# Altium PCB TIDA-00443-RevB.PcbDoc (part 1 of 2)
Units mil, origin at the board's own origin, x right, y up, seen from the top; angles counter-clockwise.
Board outline 5881 x 3685.61 mil, 2 copper layers (Top Layer, Bottom Layer), stack 62 mil thick; 123 components, 50 nets, 265 pads, 37 vias.
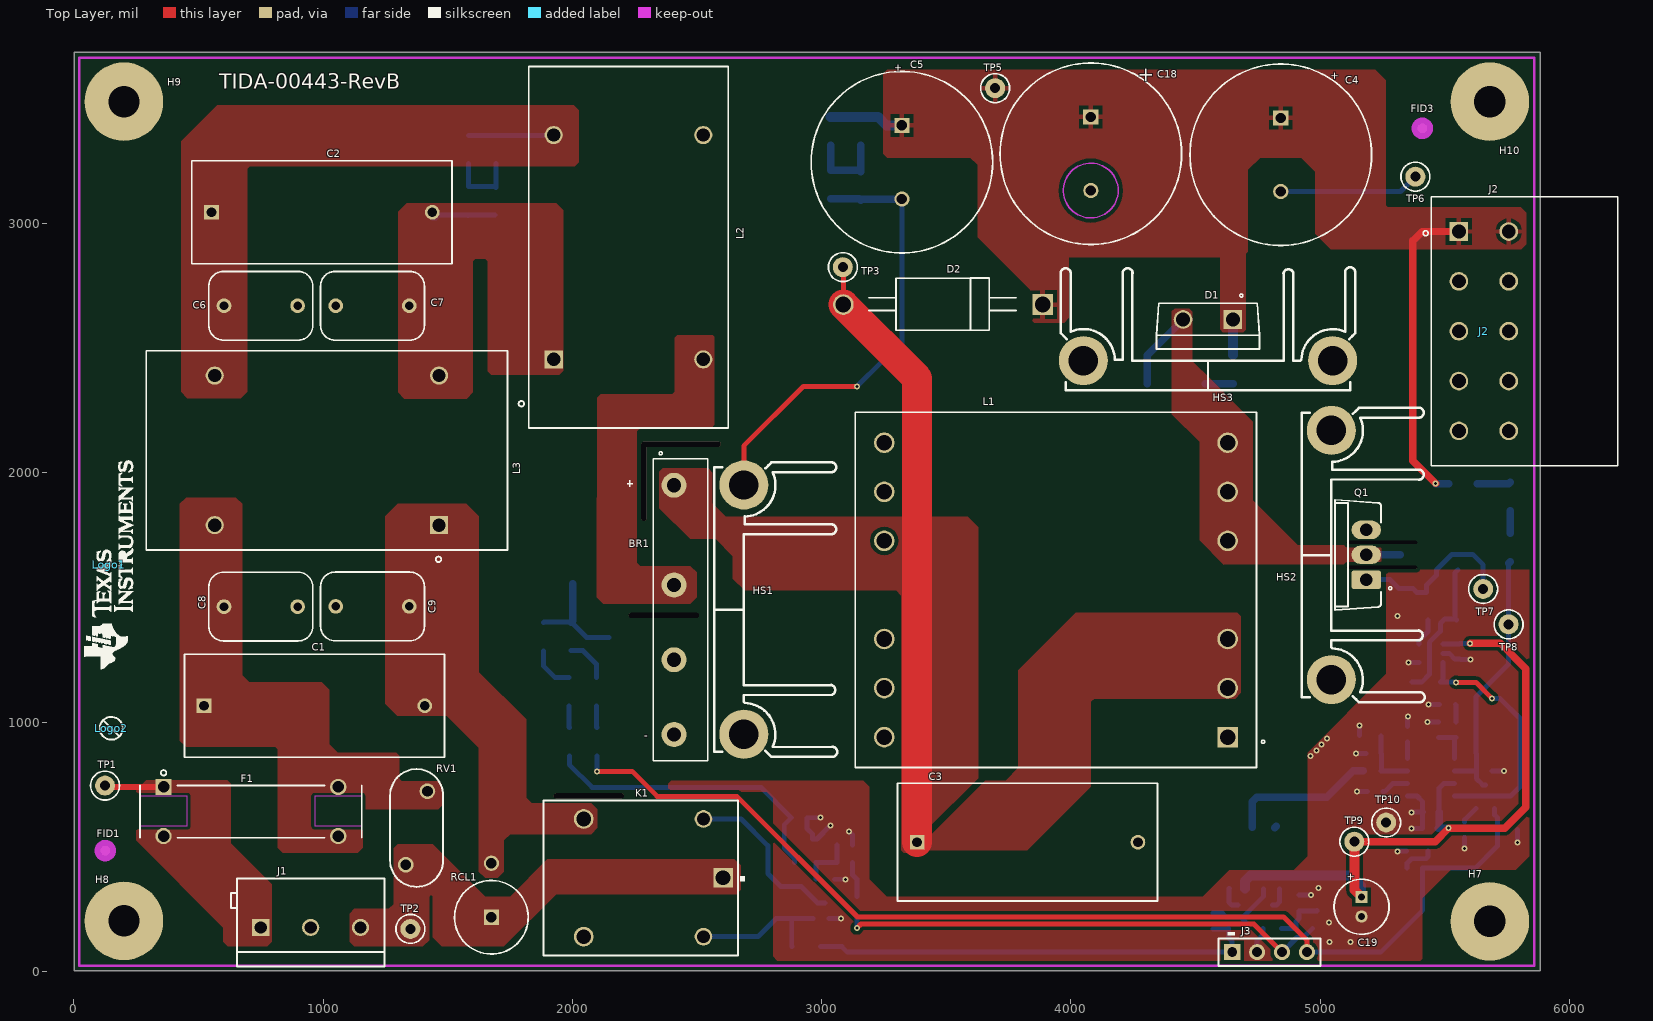
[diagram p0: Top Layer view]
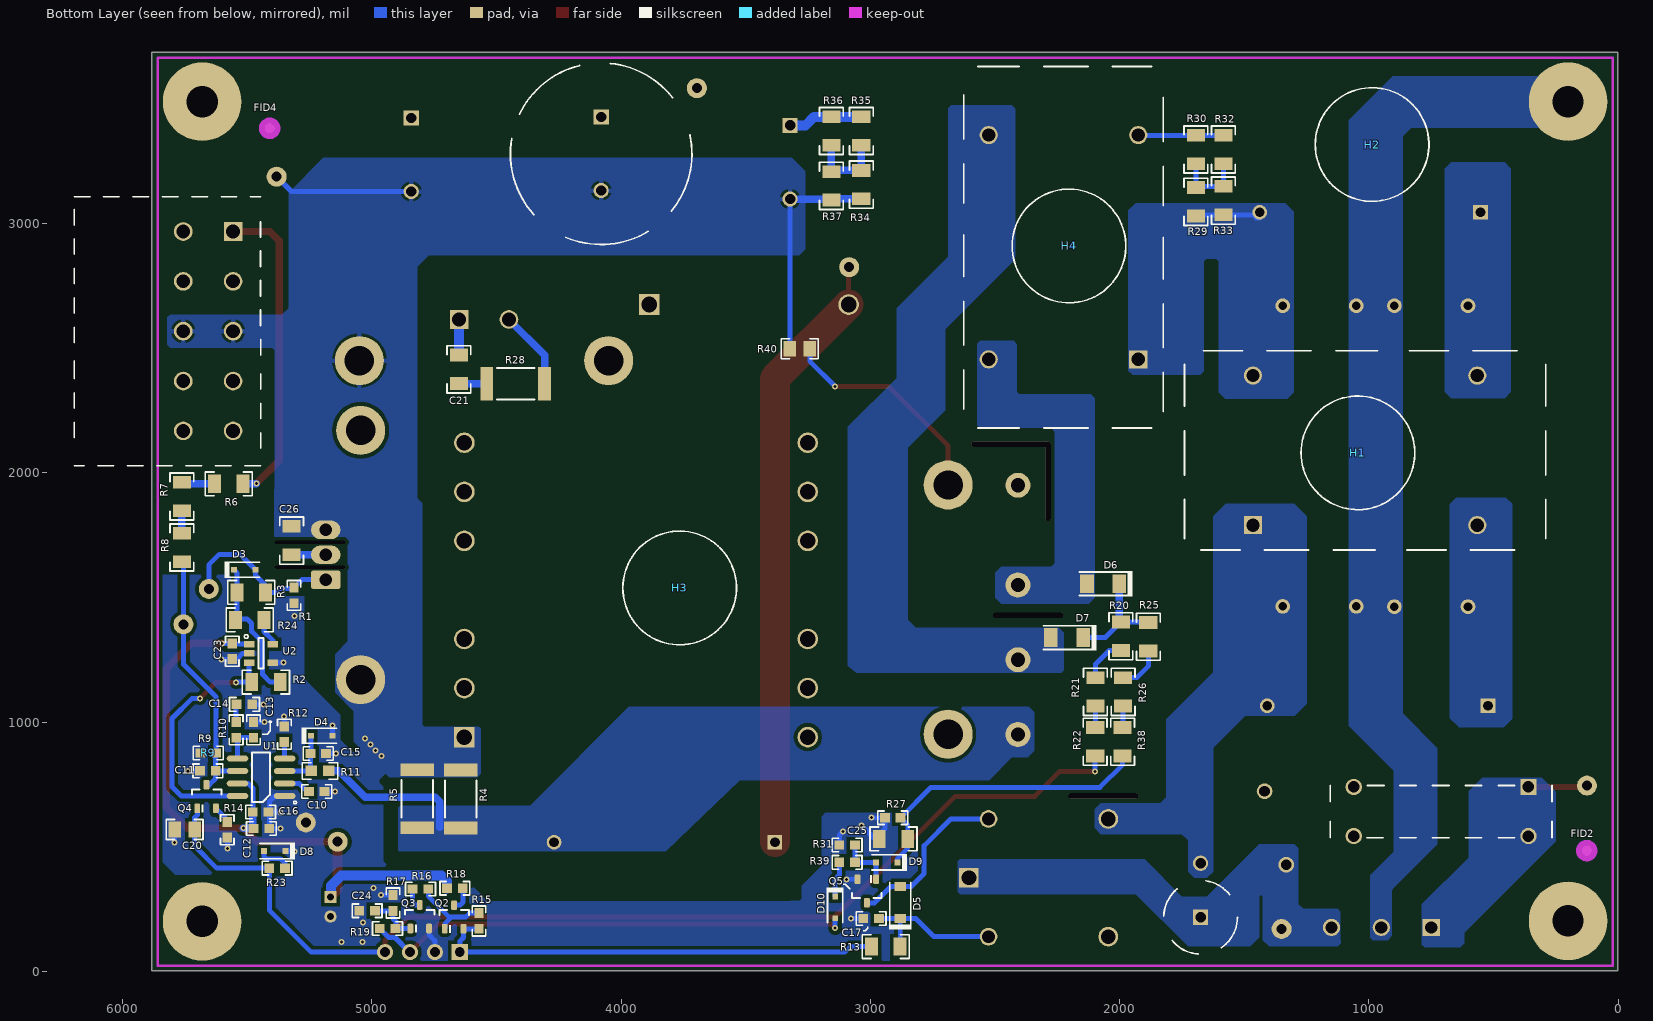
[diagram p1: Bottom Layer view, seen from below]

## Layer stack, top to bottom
Top Layer: signal copper 1.4
Dielectric: core 59.2, FR-4, Dk 4.8
Bottom Layer: signal copper 1.4

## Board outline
1,2 1,3687.61 5882,3687.61 5882,2

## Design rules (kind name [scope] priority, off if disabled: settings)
AcuteAngle [All] p1: minimum=4.50000000000000E+0001 checktracksonly=FALSE
AssemblyTestPointUsage [All] p1: valid=2
Clearance Clearance_net1 [InNet('NetC26_1') vs InPolygon] p1: gap=25
Clearance "Clearance_on net" [InNet('GNDE') vs InNetClass('All Nets')] p2: gap=120
Clearance Clearance_Pad_Via [IsPad vs IsVia] p3: gap=8
Clearance Clearance_Poly_Poly [InPolygon vs InPolygon] p4: gap=20
Clearance Clearance_Poly [InPolygon] p5: gap=15
Clearance [All] p6: gap=8
ComponentClearance ComponentClearance_MountingHoles_FiducialMarks [InComponentClass('Mounting Holes') vs InComponentClass('FiducialMark')] p1: gap=50 collisioncheckmode=3 verticalgap=10 showdistances=FALSE
ComponentClearance ComponentClearance_Shunt [InComponentClass('Header') vs InComponentClass('Shunt')] p2: gap=0 collisioncheckmode=3 verticalgap=0 showdistances=FALSE
ComponentClearance ComponentClearance_Logo [InComponentClass('Logo')] p3: gap=50 collisioncheckmode=3 verticalgap=10 showdistances=FALSE
ComponentClearance ComponentClearance_ScrewToNut [(HasFootprint('NY PMS 440 0025 PH')) vs (HasFootprint('Keystone_1902C'))] p4: gap=5 collisioncheckmode=3 verticalgap=10 showdistances=FALSE
ComponentClearance ComponentClearance_MountingHoles [InComponentClass('Mounting Holes')] p5: gap=200 collisioncheckmode=3 verticalgap=150 showdistances=FALSE
ComponentClearance ComponentClearance_SmallPassives [HasFootprint('0201*') or HasFootprint('0402*') or HasFootprint('0508') or HasFootprint('0603*') or HasFootprint('0612') or HasFootprint('0805*') or HasFootprint('0815*') or HasFootprint('0830*') or HasFootprint('1206*') or HasFootprint('1210*') or HasFootprint('1808*') or HasFootprint('1812*') or HasFootprint('1825*') or HasFootprint('2010*') or HasFootprint('2220*') or HasFootprint('2225*') or HasFootprint('2512*') or HasFootprint('2728*') or HasFootprint('3518*') vs HasFootprint('0201*') or HasFootprint('0402*') or HasFootprint('0508') or HasFootprint('0603*') or HasFootprint('0612') or HasFootprint('0805*') or HasFootprint('0815*') or HasFootprint('0830*') or HasFootprint('1206*') or HasFootprint('1210*') or HasFootprint('1808*') or HasFootprint('1812*') or HasFootprint('1825*') or HasFootprint('2010*') or HasFootprint('2220*') or HasFootprint('2225*') or HasFootprint('2512*') or HasFootprint('2728*') or HasFootprint('3518*')] p6: gap=20 collisioncheckmode=3 verticalgap=10 showdistances=FALSE
ComponentClearance ComponentClearance_THtoSMT [IsThruComponent vs IsSMTComponent] p7: gap=20 collisioncheckmode=3 verticalgap=20 showdistances=FALSE
ComponentClearance ComponentClearance_THtoTH [IsThruComponent vs IsThruComponent] p8: gap=10 collisioncheckmode=3 verticalgap=10 showdistances=FALSE
ComponentClearance [All] p9: gap=20 collisioncheckmode=3 verticalgap=10 showdistances=FALSE
DiffPairsRouting [All] p1: maxlimit=100 minlimit=10 mostfreqgap=10 maxuncoupledlength=1000
FabricationTestPointUsage TestPointUsage [All] p1: valid=2 allowmultiple=FALSE
FabricationTestpoint Testpoint [All] p1: side=3 testpointundercomponent=TRUE minsize=40 maxsize=100 preferedsize=60 minholesize=0 maxholesize=40 preferedholesize=32 testpointgrid=1 allowsidetop=TRUE allowsidebottom=TRUE usegrid=TRUE gridtolerance=0.01
FanoutControl Fanout_LCC [IsLCC] p1: bgadir=Out bgaviamode=Centered fanoutstyle=Auto fanoutdirection=Alternating viagrid=1 // Fanout_LCC (Default Rule)
FanoutControl Fanout_BGA [IsBGA] p2: bgadir=Out bgaviamode=Centered fanoutstyle=Auto fanoutdirection=Alternating viagrid=1 // Fanout_BGA (Default Rule)
FanoutControl Fanout_Default [All] p4: bgadir=Out bgaviamode=Centered fanoutstyle=Auto fanoutdirection=Alternating viagrid=1 // Fanout_Default (Default Rule)
FanoutControl Fanout_Small [(CompPinCount < 5)] p5: bgadir=Out bgaviamode=Centered fanoutstyle=Auto fanoutdirection=OutThenIn viagrid=1 // Fanout_Small (Default Rule)
Height [All] p1: minheight=0 maxheight=2100 prefheight=500
HoleSize [All] p1: absolutevalues=TRUE maxlimit=251 minlimit=8 maxpercent=80.000 minpercent=20.000
MinimumAnnularRing MinimumAnnularRing_ThermalPadVias [IsVia and InAnyComponent] p1: minimumring=5.91
MinimumAnnularRing [All] p2: minimumring=9
MinimumSolderMaskSliver MinimumSolderMaskSliver_Logo [InComponentClass('Logo') vs InComponentClass('Logo')] p1 off: minsoldermaskwidth=0.7
MinimumSolderMaskSliver [All] p2 off: minsoldermaskwidth=3.94
PlaneConnect [All] p1: planeconnectstyle=Direct reliefexpansion=10 reliefentries=4 reliefconductorwidth=10 reliefairgap=10
PolygonConnect PolygonConnect_1 [(InNetClass('New Class'))] p1: connectstyle=Relief reliefconductorwidth=20 reliefentries=4 polygonreliefangle="90 Angle" airgapwidth=10
PolygonConnect [All] p2: connectstyle=Direct reliefconductorwidth=10 reliefentries=4 polygonreliefangle="90 Angle" airgapwidth=10
RoutingVias ThermalPadVias [IsVia and InAnyComponent] p1: holewidth=7.87 width=19.68 viastyle="Through Hole" minholewidth=7.87 minwidth=19.68 maxholewidth=12.99 maxwidth=23.62
RoutingVias [All] p2: holewidth=12 width=24 viastyle="Through Hole" minholewidth=8 minwidth=18 maxholewidth=16 maxwidth=30
SilkToSilkClearance SilkToSilkClearance_Pb-FreeLogo [(HasFootprint('Pb-Free_Overlay_Medium') OR HasFootprint('Pb-Free_Overlay_Small')) vs (HasFootprint('Pb-Free_Overlay_Medium') OR HasFootprint('Pb-Free_Overlay_Small'))] p1: silktosilkclearance=0
SilkToSilkClearance [All] p2: silktosilkclearance=5
SilkscreenOverComponentPads "Silk to Solder Mask Opening" [IsPad] p1: minsilkscreentomaskgap=1
SolderMaskExpansion [All] p1: expansion=2.5
Width [All] p1: maxlimit=150 minlimit=20 preferedwidth=20 checkconnectedcopper=TRUE
13 further rules are at their usual default settings.

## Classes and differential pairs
component class "Mounting Holes": H7 H8 H9 H10
component class TIDA-00443_REVB: BR1 C1 C2 C3 C4 C5 C6 C7 C8 C9 C10 C11 C12 C13 C14 C15 C16 C17 C18 C19 C20 C21 C23 C24 C25 C26 D1 D2 D3 D4 D5 D6 D7 D8 D9 D10 F1 HS1 HS2 HS3 J1 J2 J3 K1 L1 L2 L3 Q1 Q2 Q3 Q4 Q5 R1 R2 R3 R4 R5 R6 R7 R8 R9 R10 R11 R12 R13 R14 R15 R16 R17 R18 R19 R20 R21 R22 R23 R24 R25 R26 R27 R28 R29 R30 R31 R32 R33 R34 R35 R36 R37 R38 R39 R40 RCL1 RV1 TP1 TP2 TP3 TP5 TP6 TP7 TP8 TP9 TP10 U1 U2
component class TID_Hardware: FID1 FID2 FID3 FID4 H1 H2 H3 H4 H7 H8 H9 H10 Logo2 ZZ1 ZZ2 ZZ3 ZZ4
component class FiducialMark: FID1 FID2 FID3 FID4
component class AssemblyNote: ZZ1 ZZ2 ZZ3 ZZ4
component class Header: J3
net class "New Class": VDCBUS

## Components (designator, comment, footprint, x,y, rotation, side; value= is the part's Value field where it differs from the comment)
BR1 "GBJ1508-BP" BRIDGE-TSIL_PKG 2408,1450 r270 top
C1 "B32923C3684M" B32923_16.5mm_10.5 965,1065 r0 top
C2 "B32923C3684M" B32923_16.5mm_10.5 995,3045 r0 top
C3 "B32923C3155M" B32923_22mm 3826,518 r0 top
C4 "450QXW220MEFC18X50" CAPPRD750W80D1800H5200 4842,3276 r270 top
C5 "450QXW220MEFC18X50" CAPPRD750W80D1800H5200 3322,3246 r270 top
C6 "CS11-E2GA222MYNS" CAPRD750W60D1050H1450 750,2670 r0 top
C7 "CS11-E2GA222MYNS" CAPRD750W60D1050H1450 1198,2670 r180 top
C8 "2.2nF" CAPRD750W60D1050H1450 750,1463 r0 top
C9 "2.2nF" CAPRD750W60D1050H1450 1198,1464 r180 top
C10 "06031C272JAT2A" 0603 5220.99,720.98 r180 bottom
C11 "C0603C821K5RACTU" 0603 5658,804 r0 bottom
C12 "C1608X7R1E105K080AB" 0603 5443,573 r180 bottom
C13 "C0603C394K4RACTU" 0603 5474.5,968.5 r270 bottom
C14 "GRM188R61C475KAAJ" 0603 5510.99,1070.98 r180 bottom
C15 "06031C102KAT2A" 0603 5214.99,873.98 r0 bottom
C16 "06035C104KAT2A" 0603 5446,639 r180 bottom
C17 "C1608X7R1E105K080AB" 0603 2997,212 r0 bottom
C18 "450QXW220MEFC18X50" CAPPRD750W80D1800H5200 4080,3280 r270 top
C19 "UPW1V100MDD6" PW_500x700 5166,259 r270 top
C20 "C2012X5R1E106K125AB" 0805_HV 5751,569 r0 bottom
C21 "GRM31A7U3A331JW31D" 1206 4651,2415 r270 bottom
C23 "C1608X7R1E105K080AB" 0603 5559.99,1283.98 r270 bottom
C24 "C0603C474K4RACTU" 0603 5019,243 r0 bottom
C25 "GRM319R61H475KA12" 1206 2907,531 r0 bottom
C26 "GRM31A7U3A101JW31D" 1206 5322,1728 r90 bottom
D1 "C3D04060A" TO-220-F2 4550,2615 r180 top
D2 "1N5406" DO-201AD 3487,2675 r180 top
D3 "MMDL914-TP" sod-323 5510,1610.98 r180 bottom
D4 "BAT54HT1G" sod-323 5200.99,944.98 r180 bottom
D5 "1N4148W-7-F" SOD-123 2880,276 r90 bottom
D6 "CGRM4007-G" MINI-SMA 2066,1555 r0 bottom
D7 "CGRM4007-G" MINI-SMA 2211,1339 r0 bottom
D8 "BAT54HT1G" sod-323 5390,482 r0 bottom
D9 "BZX384-C12,115" sod-323 2934,437 r0 bottom
D10 "BAT54HT1G" sod-323 3141,256 r270 bottom
F1 "01110501Z" LITTELFUSE_01110501Z 710,641 r0 top
FID1 "Fiducial" Fiducial10-20 126,484 r0 top
FID2 "Fiducial" Fiducial10-20 126,484 r180 bottom
FID3 "Fiducial" Fiducial10-20 5410,3382 r0 top
FID4 "Fiducial" Fiducial10-20 5410,3382 r180 bottom
H1 "SJ-5303 (CLEAR)" Bumpon_SJ5003Transparent 1044,2080 r180 bottom
H2 "SJ-5303 (CLEAR)" Bumpon_SJ5003Transparent 987,3317 r180 bottom
H3 "SJ-5303 (CLEAR)" Bumpon_SJ5003Transparent 3765,1538 r180 bottom
H4 "SJ-5303 (CLEAR)" Bumpon_SJ5003Transparent 2203,2910 r180 bottom
H7 "NY PMS 440 0025 PH" "NY PMS 440 0025 PH" 5681,200 r0 top locked
H8 "NY PMS 440 0025 PH" "NY PMS 440 0025 PH" 201,202 r0 top
H9 "NY PMS 440 0025 PH" "NY PMS 440 0025 PH" 201,3489 r0 top
H10 "NY PMS 440 0025 PH" "NY PMS 440 0025 PH" 5681,3489 r0 top locked
HS1 "V6560Y" HS_ASS_0595 2688,1451 r270 top
HS2 "V6560Y" HS_ASS_0595 5045,1670 r270 top
HS3 "V6560Y" HS_ASS_0595 4550,2450 r0 top
J1 "ED120/3DS" CONN_ED120_3DS 950,176 r90 top
J2 "1786433" PHOENIX_1786433 5820,2568 r90 top
J3 "PEC04SAAN" SULLINS_PEC04SAAN 4796.98,77.03 r0 top
K1 "G5LE-1A4 DC12" RELAY_G5LA-1 2325,375 r270 top
L1 "750342810" WE_750342810 3940,1530 r180 top
L2 "5 mH" IND_8113-RC 2225,2905 r180 top
L3 "5 mH" IND_8113-RC 1015,2090 r270 top
Logo1 "Texas Instruments" TI_Stacked_Overlay_Small 139,1631 r90 top
Logo2 "Pb-Free Symbol" Pb-Free_Overlay_Small 150,975 r0 top
Q1 "IPP60R190P6" TO-220AB 5185,1671 r90 top
Q2 "MMBT3906" SOT-23 4670,218 r90 bottom
Q3 "2N7002-7-F" SOT-23 4808,219 r90 bottom
Q4 "BC847CLT1G" SOT-23 5663,701 r90 bottom
Q5 "2N7002-7-F" SOT-23 3014,322 r270 bottom
R1 "CRCW060310K0FKEA" 0603 5312,1508 r270 bottom
R2 "CRCW12063R90JNEA" 1206 5424.99,1159.98 r180 bottom
R3 "CRCW12061R05FKEA" 1206 5483.99,1519.98 r180 bottom
R4 "CRA2512-FZ-R020ELF" 2512 4643,691 r270 bottom
R5 "CSRN2512FKR200" 2512 4818,692 r270 bottom
R6 "CRCW1206332KFKEA" 1206 5574,1956 r180 bottom
R7 "CRCW1206332KFKEA" 1206 5762,1905 r90 bottom
R8 "CRCW1206340KFKEA" 1206 5762,1700 r90 bottom
R9 "CRCW060313K0FKEA" 0603 5656,876 r180 bottom
R10 "CRCW060323K7FKEA" 0603 5544.5,968.5 r90 bottom
R11 "CRCW0603221RFKEA" 0603M 5207.99,803.98 r0 bottom
R12 "CRCW060321K5FKEA" 0603 5350.99,950.98 r90 bottom
R13 "CRCW1206100RFKEA" 1206 2938,99 r180 bottom
R14 "CRCW060313K7FKEA" 0603 5580,568 r270 bottom
R15 "CRCW060310K0FKEA" 0603 4570,202 r90 bottom
R16 "CRCW06036K80JNEA" 0603 4805,330 r180 bottom
R17 "CRCW0603100KFKEA" 0603 4915,274 r270 bottom
R18 "CRCW060315R4FKEA" 0603 4667,333 r0 bottom
R19 "CRCW06032K21FKEA" 0603 4937,172 r180 bottom
R20 "CRCW1206332KFKEA" 1206 1995,1344 r90 bottom
R21 "CRCW1206332KFKEA" 1206 2097,1121 r270 bottom
R22 "CRCW1206340KFKEA" 1206 2098,921 r90 bottom
R23 "CRCW060310K0FKEA" 0603 5380,414 r180 bottom
R24 "CRCW12062R10FKEA" 1206 5489.99,1409.98 r180 bottom
R25 "CRCW1206340KFKEA" 1206 1885,1342 r90 bottom
R26 "CRCW1206340KFKEA" 1206 1986,1121 r270 bottom
R27 "CRCW0603221KFKEA" 0603 2910,616 r180 bottom
R28 "CRM2512-FX-43R2ELF" 2512 4423,2356.89 r0 bottom
R29 "CRCW1206221KFKEA" 1206 1693.64,3087.06 r270 bottom
R30 "CRCW1206221KFKEA" 1206 1693.64,3297.06 r270 bottom
R31 "CRCW060347K5FKEA" 0603 3093,507 r180 bottom
R32 "CRCW1206221KFKEA" 1206 1583.64,3297.06 r270 bottom
R33 "CRCW1206221KFKEA" 1206 1583.64,3092.06 r270 bottom
R34 "CRCW1206221KFKEA" 1206 3036.36,3156.06 r90 bottom
R35 "CRCW1206221KFKEA" 1206 3036.36,3371.06 r90 bottom
R36 "CRCW1206221KFKEA" 1206 3156.36,3371.06 r90 bottom
R37 "CRCW1206221KFKEA" 1206 3156.36,3151.06 r90 bottom
R38 "CRCW120621K0FKEA" 1206 1988,921 r270 bottom
R39 "CRCW06031K00FKEA" 0603 3093,437 r180 bottom
R40 "CRCW08050000Z0EA" 0805_HV 3283,2498 r180 bottom
RCL1 "AC07000002009JAC00" RESADV550W80L2600D750B 1675,325 r90 top
RV1 "S10K275E2" VAR_S10K275E2 1375,575 r90 top
TP1 "5000" Keystone5000 125,745 r0 top
TP2 "5000" Keystone5000 1350,170 r0 top
TP3 "5000" Keystone5000 3085,2825 r0 top
TP5 "5000" Keystone5000 3696,3543 r0 top
TP6 "5001" Keystone5001 5382,3188 r0 top
TP7 "5000" Keystone5000 5654,1534 r90 top
TP8 "5000" Keystone5000 5756,1392 r90 top
TP9 "5000" Keystone5000 5137,520 r90 top
TP10 "5001" Keystone5001 5265,597 r0 top
U1 "UCC28180D" D0008A_N 5444.5,778.5 r0 bottom
U2 "UCC27517ADBV" DBV0005A_N 5444.75,1275.38 r180 bottom
ZZ1 "This Assembly Note is for PCB labels only" AssemblyNoteLabel 452,3855 r0 top
ZZ2 "These assemblies are ESD sensitive, ESD precautions shall be observed." AssemblyNote 453,3923 r0 top
ZZ3 "These assemblies must be clean and free from flux and all contaminants. Use of no clean flux is not acceptable." AssemblyNote 451,3988 r0 top
ZZ4 "These assemblies must comply with workmanship standards IPC-A-610 Class 2, unless otherwise specified." AssemblyNote 458,4054 r0 top

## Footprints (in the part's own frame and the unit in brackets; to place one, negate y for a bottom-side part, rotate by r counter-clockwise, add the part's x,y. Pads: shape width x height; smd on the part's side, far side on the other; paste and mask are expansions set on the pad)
0603 [mm] "0603 from SM-752 data"
  rect 1x0.95 smd: 1(-0.8,0) 2(0.8,0)
  silkscreen extent -1.52,-0.69 1.52,0.69, body extent -0.87,-0.47 0.87,0.47, height 0.85
0603M [mm] "0603 from SM-752 data"
  rect 1.2x1.05 smd: 1(-0.9,0) 2(0.9,0)
  silkscreen extent -1.82,-0.84 1.82,0.84, body extent -0.87,-0.47 0.87,0.47, height 0.85
0805_HV [mil] "0805 with 30mil clearance between pads"
  rect 50x63 smd: 1(-40,0) 2(40,0)
  silkscreen extent -74,-40 74,40, body extent -43,-29 43,29, height 43
1206 [mm] "1206 from SM-752 data"
  rect 1.3x1.85 smd: 1(-1.45,0) 2(1.45,0)
  silkscreen extent -2.4,-1.21 2.4,1.21, body extent -1.7,-0.9 1.7,0.9, height 1.35
2512 [mm] "Chip Resistor, Body 6.3x3.2mm, IPC Medium Density"
  rect 1.3x3.4 smd: 1(-2.95,0) 2(2.95,0)
  silkscreen extent -1.9,-1.6 1.9,1.6, body extent -3.22,-1.67 3.22,1.67, height 0.71
AssemblyNote [mil] "Assembly Note"
AssemblyNoteLabel [mil] "Assembly Note for PCB Labels"
B32923_16.5mm_10.5 [mm] "Epcos film capacitors, 22.5mm spacing"
  rect 1.5x1.5 hole 1: 1(-11.25,0)
  round 1.5 hole 1: 2(11.25,0)
  silkscreen extent -13.25,-5.25 13.25,5.25, body extent -13.25,-5.25 13.25,5.25, height 16.5
B32923_22mm [mm] "Epcos film capacitors, 22.5mm spacing"
  rect 1.5x1.5 hole 1: 1(-11.25,0)
  round 1.5 hole 1: 2(11.25,0)
  silkscreen extent -13.25,-6 13.25,6, body extent -13.25,-6 13.25,6, height 22
BRIDGE-TSIL_PKG [mil]
  round 100 hole 57: 1(-500,0) 2(-100,0) 3(200,0) 4(500,0)
Bumpon_SJ5003Transparent [mil] "3M Hemispherical Bumpon transparent"
  round 1 on Mech4: 0(0,0)
  silkscreen extent -228,-228 228,228, body extent -217,-218 219,218, height 197
CAPPRD750W80D1800H5200 [mm] "Capacitor, Aluminum Electrolytic, Radial; Body 18 x 50 mm (Dia.xH typ); Pin Spacing 7.5 mm (typ)"
  rect 1.554x1.554 hole 1.054: 1(-3.75,0)
  round 1.554 hole 1.054: 2(3.75,0)
  silkscreen extent -9.25,-9.25 9.25,9.25, body extent -9.18,-9.23 9.25,9.23, height 52
CAPRD750W60D1050H1450 [mm] "TDK"
  round 1.5 hole 0.889: 1(-3.75,0) 2(3.75,0)
  silkscreen extent -5.3,-3.5 5.3,3.5, body extent -5.24,-3.5 5.24,3.5, height 14.46
CONN_ED120_3DS [mm] "ONSHORE"
  rect 1.75x1.75 hole 1.25: 1(0,5.08)
  round 1.75 hole 1.25: 2(0,0) 3(0,-5.08)
  silkscreen extent -4,-7.5 5,8.14, body extent -4.13,-7.55 5.05,8.14, height 13.1
D0008A_N [mm] "SOIC, 8-Leads, Body 4.9x3.9mm, Pitch 1.27mm, IPC Medium Density"
  oval 2.2x0.6 smd: 1(-2.4,1.905) 2(-2.4,0.635) 3(-2.4,-0.635) 4(-2.4,-1.905) 5(2.4,-1.905) 6(2.4,-0.635) 7(2.4,0.635) 8(2.4,1.905)
  silkscreen extent -0.9,-2.5 0.9,2.5, body extent -3,-2.45 3,2.45, height 1.63
DBV0005A_N [mm] "SOT23, 5-Leads, Body 2.9x1.6mm, Pitch 0.95mm, Lead Span 2.8mm, IPC Medium Density"
  rect 1.1x0.65 smd: 1(-1.2,0.95) 2(-1.2,0) 3(-1.2,-0.95) 4(1.2,-0.95) 5(1.2,0.95)
  silkscreen extent -0.25,-1.55 0.25,1.55, body extent -1.42,-1.46 1.42,1.46, height 1.08
DO-201AD [mm] "Vishay dimensions"
  rect 2.1x2.1 hole 1.6: 1(-10.16,0)
  round 2.1 hole 1.6: 2(10.16,0)
  silkscreen extent -7.47,-2.7 7.57,2.61, body extent -10.82,-2.74 10.82,2.61, height 5.33
Fiducial10-20 [mm]
  round 1 smd mask+0.5: 1(0,0)
  Top Layer keep-out circle w1.178: c0,0 r0.5
HS_ASS_0595 [mm]
  round 5 hole 3: 1(-12.7,0) 2(12.7,0)
  silkscreen extent -15.02,-3 15,9.51, body extent -15.18,-3.1 15.2,9.5, height 50
IND_8113-RC [mm] "INDUCTOR, CHOKE, COMMON MODE, 4 PIN, TH"
  rect 1.85x1.85 / inner round 1.85 / far side rect 1.85x1.85 hole 1.35 paste+0 mask+0.064: 1(7.62,11.43)
  round 1.85 hole 1.35 paste+0 mask+0.064: 2(-7.62,11.43) 3(-7.62,-11.43) 4(7.62,-11.43)
  silkscreen extent -10.16,-18.41 11.2,18.41, body extent -10.16,-18.41 10.16,18.41, height 38.1
Keystone5000 [mil] "For Keystone 500x miniature loop terminals"
  round 80 hole 40: 1(0,0)
  silkscreen extent -58,-58 58,58, body extent -49,-49 49,49, height 182
Keystone5001 [mil] "For Keystone 500x miniature loop terminals"
  round 80 hole 40: 1(0,0)
  silkscreen extent -58,-58 58,58, body extent -49,-49 49,49, height 182
LITTELFUSE_01110501Z [mm] "FUSE CLIP, CARTRIDGE, 250V, 10A, PCB"
  rect 1.67x1.67 / inner round 1.67 / far side rect 1.67x1.67 hole 1.17: 1(-8.9,2.5)
  round 1.67 hole 1.17: 2(-8.9,-2.5) 3(8.9,2.5) 4(8.9,-2.5)
  Top Layer keep-out region: 6.508,-1.467 11.308,-1.467 11.308,1.533 6.508,1.533
  Top Layer keep-out region: -11.292,-1.467 -6.492,-1.467 -6.492,1.533 -11.292,1.533
  silkscreen extent -11.3,-2.66 11.3,4.22, body extent -11.3,-2.66 11.3,2.66, height 7.1
MINI-SMA [mm] "COMCHIP"
  rect 1.4x1.9 smd: 1(-1.65,0) 2(1.65,0)
  silkscreen extent -3,-1.3 2.4,1.3, body extent -1.95,-0.9 1.95,0.9, height 1.7
"NY PMS 440 0025 PH" [mm] "4-40 nylon screw and mounting hole"
  round 8 hole 3.2: 1(0,0)
  body extent -3.3,-3.3 3.3,3.3, height 2.69
Pb-Free_Overlay_Small [mil]
  silkscreen extent -46,-46 46,46
PHOENIX_1786433 [mm] "TERM BLOCK, HDR, 5POS, R/A 5.08MM"
  round 1.9 hole 1.4: 1(10.16,1.61) 2(5.08,6.69) 2(5.08,1.61) 3(0,6.69) 3(0,1.61) 4(-5.08,6.69) 4(-5.08,1.61) 5(-10.16,1.61) 5(-10.16,6.69)
  rect 1.9x1.9 / inner round 1.9 / far side rect 1.9x1.9 hole 1.4: 1(10.16,6.69)
  silkscreen extent -13.7,-9.5 13.7,10.34, body extent -13.72,-9.52 13.72,9.53, height 10.2
PW_500x700 [mm] "Nichicon"
  rect 1.25x1.25 hole 0.711: 1(-1,0)
  round 1.25 hole 0.711: 2(1,0)
  silkscreen extent -2.8,-2.8 2.8,2.8, body extent -2.73,-2.75 2.75,2.75, height 8.01
RELAY_G5LA-1 [mm] "TH, 4-Leads, Body 19.8x15.8mm"
  rect 2x2 hole 1.5: 1(0,7.1)
  round 1.8 hole 1.3: 2(-6,5.1) 5(6,5.1)
  round 2 hole 1.5: 3(-6,-7.1) 4(6,-7.1)
  silkscreen extent -7.9,-11.2 7.9,9.32, body extent -7.9,-11.2 7.9,8.6, height 15.8
RESADV550W80L2600D750B [mm] "RESISTOR, WIREWOUND, TH-2P, VERTICAL MOUNT"
  rect 1.554x1.554 / inner round 1.554 / far side rect 1.554x1.554 hole 1.054: 1(-2.75,0)
  round 1.554 hole 1.054: 2(2.75,0)
  silkscreen extent -6.5,-3.75 1,3.75, body extent -6.47,-3.74 1,3.74, height 29
SOD-123 [mm] "On Semi recommended land pattern"
  rect 0.915x1.22 smd: 1(-1.637,0) 2(1.637,0)
  silkscreen extent -2.74,-1.17 2.03,1.17, body extent -1.93,-0.9 1.93,0.9, height 1.35
sod-323 [mm] "NXP recommended land pattern"
  rect 0.6x0.6 smd paste-0.05: 1(-1.1,0) 2(1.1,0)
  silkscreen extent -2.06,-0.86 1.53,0.86, body extent -1.3,-0.67 1.3,0.68, height 1.1
SOT-23 [mm] "SOT23, 3-Leads, Body 2.9x1.3mm, Pitch 0.95mm, Lead Span 2.5mm, IPC Medium Density"
  rrect50% 1x0.6 smd: 1(-1.2,0.95) 2(-1.2,-0.95) 3(1.2,0)
  silkscreen extent -1.63,-1.5 0.7,1.5, body extent -1.16,-1.45 1.21,1.45, height 1
SULLINS_PEC04SAAN [mm] "SULLINS"
  rect 1.65x1.65 hole 1: 1(-3.81,0)
  round 1.65 hole 1: 2(-1.27,0) 3(1.27,0) 4(3.81,0)
  silkscreen extent -5.21,-1.4 5.21,2.06, body extent -5.21,-1.33 5.21,1.33, height 8.38
TI_Stacked_Overlay_Small [mil]
  silkscreen extent -418,-98 418,98
TO-220-F2 [mm] "CREE"
  rect 1.9x1.9 hole 1.4: 1(-2.54,0)
  round 1.9 hole 1.4: 2(2.54,0)
  silkscreen extent -5.25,-1.64 5.26,3.01, body extent -5.25,-1.64 5.26,3.01, height 19.09
TO-220AB [mil] "Copied from Altium's version of TO3B"
  rrect25% 74x118.11 hole 50 mask+2: 1(-100,0)
  oval 74x118.11 hole 50 mask+2: 2(0,0) 3(100,0)
  silkscreen extent -221,-59 221,126, body extent -221,-59 221,126, height 765
VAR_S10K275E2 [mm] "EPCOS"
  round 1.6 hole 1.1: 1(-3.75,1.1) 2(3.75,-1.1)
  silkscreen extent -6,-2.7 6,2.7, body extent -5.98,-2.7 5.98,2.7, height 14.99
WE_750342810 [mm] "INDUCTOR, TH, 12-PIN"
  rect 2.1x2.1 / inner round 2.1 / far side rect 2.1x2.1 hole 1.6: 1(-17.5,15)
  round 2.1 hole 1.6: 2(-17.5,10) 3(-17.5,5) 4(-17.5,-5) 5(-17.5,-10) 6(-17.5,-15) 7(17.5,-15) 8(17.5,-10) 9(17.5,-5) 10(17.5,5) 11(17.5,10) 12(17.5,15)
  silkscreen extent -20.45,-18.1 20.45,18.1, body extent -20.45,-18.1 20.45,18.1, height 39.63

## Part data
BR1: library part D-BRIDGE_GBJ_15A_SERIES, "Diode, Bridge Rectifier, GPP 15A 800V GBJ"
C1 C2: "CAP, Film, 0.68 µF, 630 V, +/- 20%, TH"
C3: "CAP, Film, 1.5 µF, 630 V, +/- 20%, 0.017 ohm, TH"
C4 C5 C18: "CAP, ALUMINIUM, RADIAL, 220 uF, 450 V, 20%, TH"
C6 C7: "CAP, CERM, 2200 pF, 250 V, +/- 20%, E, Radial Disc D10.5x7mm"
C8 C9: library part CS11-E2GA222MYNS, "CAP, CERM, 2200 pF, 250 V, +/- 20%, E, Radial Disc D10.5x7mm"
C10: "CAP, CERM, 2700 pF, 100 V, +/- 5%, X7R, 0603"
C11: "CAP, CERM, 820 pF, 50 V, +/- 10%, X7R, 0603"
C12 C17 C23: "CAP, CERM, 1 µF, 25 V, +/- 10%, X7R, 0603"
C13: "CAP, CERM, 0.39 µF, 16 V, +/- 10%, X7R, 0603"
C14: "CAP, CERM, 4.7 µF, 16 V, +/- 10%, X5R, 0603"
C15: "CAP, CERM, 1000 pF, 100 V, +/- 10%, X7R, 0603"
C16: "CAP, CERM, 0.1 µF, 50 V, +/- 10%, X7R, 0603"
C19: "CAP, AL, 10uF, 35V, +/-20%, 0.95 ohm, TH"
C20: "CAP, CERM, 10 µF, 25 V, +/- 10%, X5R, 0805"
C21: "CAP, CERM, 330 pF, 1000 V, +/- 5%, U2J, 1206"
C24: "CAP, CERM, 0.47 µF, 16 V, +/- 10%, X7R, 0603"
C25: "CAP, CERM, 4.7 µF, 50 V, +/- 10%, X5R, 1206"
C26: "CAP, CERM, 100 pF, 1000 V, +/- 5%, U2J, 1206"
D1: "Diode, Schottky, 600 V, 4 A, TH"
D2: "Diode, Switching-Bridge, 600 V, 3 A, TH"
D3: "Diode, Switching, 100 V, 0.2 A, SOD-323"
D4 D8 D10: "Diode, Schottky, 30V, 0.2A, SOD-323"
D5: "Diode, Ultrafast, 100V, 0.15A, SOD-123"
D6 D7: "Diode, P-N, 1000 V, 1 A, 3.9x1.7x1.8mm"
D9: "Diode, Zener, 12V, 300mW, SOD-323"
F1: "FUSE CLIP, CARTRIDGE, 250V, 10A, PCB"
FID1 FID2 FID3 FID4: "Fiducial mark.  There is nothing to buy or mount."
H1 H2 H3 H4: "Bumpon, Hemisphere, 0.44 X 0.20, Clear"
H7 H8 H9 H10: "Machine Screw, Round, #4-40 x 1/4, Nylon, Philips panhead"
HS1 HS2 HS3: library part 531002B02500G, "HEATSINK ALUM Black Anodized, Board Mount"
J1: "TERMINAL BLOCK 5.08MM VERT 3POS, TH"
J2: "TERM BLOCK HDR 5POS R/A 5.08MM"
J3: "Header, 100mil, 4x1, Tin, TH"
K1: library part "G5LA-14 DC5", "Relay, SPDT (1 Form C), 5A, 5 VDC, TH"
L1: "INDUCTOR, 360 uH, 8.3 A, 10%, TH"
L2 L3: library part 8113-RC, "INDUCTOR, CHOKE, COMMON MODE, 5 mH, 8.9 A, 22 mOHM, TH"
Logo1: library part TI_Logo, "Texas Instrument Corporate Signature"
Logo2: library part Pb-Free
Q1: "MOSFET, N-CH, 600 V, 20.2 A, TO-220"
Q2: library part "MMBT3906, Fairchild Semiconductor", "Transistor, PNP, 40V, 0.2A, SOT-23"
Q3 Q5: "MOSFET, N-CH, 60V, 0.17A, SOT-23"
Q4: library part "BC847CLT1G, ON Semiconductor", "Transistor, NPN, 45 V, 0.1 A, SOT-23"
R1 R23: "RES, 10.0 k, 1%, 0.1 W, 0603"
R2: "RES, 3.9, 5%, 0.25 W, 1206"
R3: "RES, 1.05, 1%, 0.25 W, 1206"
R4: "RES, 0.02, 1%, 3 W, 2512"
R5: "RES, 0.2, 1%, 2 W, 2512"
R6 R7 R20 R21: "RES, 332 k, 1%, 0.25 W, 1206"
R8 R22 R25 R26: "RES, 340 k, 1%, 0.25 W, 1206"
R9: "RES, 13.0 k, 1%, 0.1 W, 0603"
R10: "RES, 23.7 k, 1%, 0.1 W, 0603"
R11: "RES, 221 ohm, 1%, 0.1W, 0603"
R12: "RES, 21.5 k, 1%, 0.1 W, 0603"
R13: "RES, 100, 1%, 0.25 W, 1206"
R14: "RES, 13.7 k, 1%, 0.1 W, 0603"
R15: "RES, 10.0k ohm, 1%, 0.1W, 0603"
R16: "RES, 6.8 k, 5%, 0.1 W, 0603"
R17: "RES, 100 k, 1%, 0.1 W, 0603"
R18: "RES, 15.4, 1%, 0.1 W, 0603"
R19: "RES, 2.21 k, 1%, 0.1 W, 0603"
R24: "RES, 2.10, 1%, 0.25 W, 1206"
R27: "RES, 221 k, 1%, 0.1 W, 0603"
R28: library part CRCW2512100RFKEG, "RES, 100, 1%, 1 W, 2512"
R29 R30 R32 R33 R34 R35 R36 R37: "RES, 221 k, 1%, 0.25 W, 1206"
R31: "RES, 47.5 k, 1%, 0.1 W, 0603"
R38: "RES, 21.0 k, 1%, 0.25 W, 1206"
R39: "RES, 1.00 k, 1%, 0.1 W, 0603"
R40: "RES, 0, 5%, 0.125 W, 0805"
RCL1: "RES 10 OHM 7W 5% AXIAL"
RV1: "Varistor 275V RMS 10MM Radial, TH"
TP1 TP2 TP3 TP5 TP7 TP8 TP9: "Test Point, Miniature, Red, TH"
TP6 TP10: "Test Point, Miniature, Black, TH"
U1: "8-PIN CONTINUOUS CONDUCTION MODE (CCM) PFC CONTROLLER, D0008A"
U2: library part UCC27517DBV, "IC, 4A Single Channel High-Speed Low-Side Gate Drivers"
ZZ1: library part AssemblyNoteLabel
ZZ2 ZZ3 ZZ4: library part AssemblyNote

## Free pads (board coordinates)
  oval 282x20 hole 20 slot 282 at 0 deg unplated mask+5: 3(2066,704) 3(2367,1428)
  oval 20x317 hole 20 slot 317 at 90 deg unplated mask+5: 3(2287,1966)
  oval 317x20 hole 20 slot 317 at 0 deg unplated mask+5: 3(2436,2115)
  oval 282x12 hole 12 slot 282 at 0 deg unplated mask+2: 3(5248,1621) 3(5248,1721)

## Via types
v1: diameter 24, hole 12, Top Layer to Bottom Layer, tented both sides, 37 vias

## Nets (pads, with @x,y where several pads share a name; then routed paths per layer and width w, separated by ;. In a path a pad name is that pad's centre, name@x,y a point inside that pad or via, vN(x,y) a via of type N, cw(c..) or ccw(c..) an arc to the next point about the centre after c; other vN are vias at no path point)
ACSENSE: C20.1 J3.4 Q4.1 R22.1 R23.1 | length 4433
  Top Layer w20: v1(2099,802) 2240,802 2340,702 2660,702 3144,218 4853.89,218 4946.98,124.92 J3.4@4946.98,77.03
  Bottom Layer w20: R22.1@2098,863.91 2098,803 v1(2099,802) ; J3.4@4946.98,77.03 5243.03,77.03 5411.5,245.5 R23.1@5411.5,414 5622,414 5711,503 C20.1@5711,569 5711,616.99 5700.4,627.59 Q4.1@5700.4,653.76
BIAS: J3.1 Q2.2 R13.1 R15.1 | length 1823.4
  Bottom Layer w20: R13.1@2995.09,99 3081,99 3102.97,77.03 J3.1@4646.98,77.03 4646.98,121.05 4632.6,135.43 Q2.2@4632.6,170.76 4632.35,170.5 R15.1@4570,170.5
GNDE: C6.2 C7.2 C8.2 C9.2 H9.1 J1.2
NetBR1_1: BR1.1 C3.1 D2.2 L1.2 L1.3 TP3.1 | length 2422.1
  Top Layer w20: D2.2@3087,2675 3088,2676 TP3.1@3088,2817
  Top Layer w120: D2.2@3087,2675 3383.09,2378.91 C3.1@3383.09,518
NetBR1_2: BR1.2 D6.2 L2.2
NetBR1_3: BR1.3 D7.2 L2.3
NetC1_1: C1.1 C8.1 F1.3 F1.4 L3.4 RV1.2
NetC1_2: C1.2 C9.1 K1.3 L3.1 RCL1.2
NetC2_1: C2.1 C6.1 L2.4 L3.3 R30.1 R32.1 | length 341.7
  Bottom Layer w20: R32.1@1583.64,3354.14 R30.1@1693.64,3354.14 1924.14,3354.14 L2.4@1925,3355
NetC2_2: C2.2 C7.1 L2.1 L3.2 R29.2 R33.2 | length 271.8
  Bottom Layer w20: C2.2@1437.91,3023 C2.2@1452,3023 ; C2.2@1437.91,3045 1447.94,3034.97 R33.2@1583.64,3034.97 ; R33.2@1581.67,3033 R33.2@1583.64,3034.97 ; R29.2@1688.64,3034.97 R33.2@1583.64,3034.97
NetC10_1: C10.1 U1.2 | length 111
  Bottom Layer w20: C10.1@5252.49,720.98 5258.98,720.98 5291.5,753.5 U1.2@5350.02,753.5
NetC13_2: C13.2 R10.1 U1.5 | length 155.8
  Bottom Layer w20: C13.2@5474.5,937 R10.1@5544.5,937 5538.99,931.49 U1.5@5538.99,853.5
NetC14_1: C14.1 R10.2 | length 71.8
  Bottom Layer w20: C14.1@5542.49,1070.98 5544.5,1068.96 R10.2@5544.5,999.99
NetC15_2: C15.2 D4.1 R11.2 U1.3 | length 250
  Bottom Layer w20: D4.1@5244.3,944.98 5244.3,876.17 C15.2@5246.49,873.98 5246.49,807.04 R11.2@5243.42,803.98 5349.54,803.98 U1.3@5350.02,803.5
NetC17_1: C17.1 D5.1 K1.5 R13.2 | length 583
  Bottom Layer w20: K1.5@2525.79,138.78 2744.78,138.78 2817.53,211.53 D5.1@2880,211.53 ; R13.2@2880.91,99 2880,99.91 D5.1@2880,211.53 ; C17.1@2965.5,212 2965.04,211.53 D5.1@2880,211.53
NetC21_2: C21.2 R28.2 | length 112.3
  Bottom Layer w30: R28.2@4539.14,2356.89 4649.98,2356.89 C21.2@4651,2357.91
NetC24_1: C24.1 Q3.1 R17.2 R19.2 | length 209.2
  Bottom Layer w20: Q3.1@4845.4,171.76 4905.26,171.76 4903,174.02 4903,199.27 4915,211.27 R17.2@4915,242.5 4987.01,242.5 C24.1@4987.5,243
NetC25_1: C25.1 D9.1 R27.2 R38.2 | length 1221.4
  Bottom Layer w20: R38.2@1988,863.91 1988,829 2079,738 2756.5,738 R27.2@2878.5,616 2849.91,587.41 C25.1@2849.91,531 2849.91,494.09 2890.69,453.31 D9.1@2890.69,437
NetC26_1: C26.1 D1.2 L1.4 L1.5 L1.6 Q1.2 R28.1 | length 454.4
  Bottom Layer w30: R28.1@4306.86,2356.89 4306.86,2471.86 D1.2@4450,2615 ; Q1.2@5185,1671 5321.91,1671 C26.1@5322,1670.91
NetD3_1: D3.1 R2.2 R3.1 R24.1 | length 579.9
  Bottom Layer w20: R2.2@5367.9,1159.98 5406.98,1159.98 5438,1191 5438,1319.81 5482.09,1363.91 5482.09,1395.09 5501,1414 5543.05,1414 R24.1@5547.08,1409.98 ; R24.1@5541.08,1415.98 R3.1@5541.08,1519.98 5541.08,1598.75 D3.1@5553.31,1610.98
NetD3_2: D3.2 Q1.1 R1.1 R3.2 TP7.1 | length 697.9
  Bottom Layer w20: Q1.1@5185,1571 5280,1571 5314.5,1536.5 5371.5,1536.5 5388.02,1519.98 R3.2@5426.9,1519.98 5426.9,1548.9 5466.69,1588.69 D3.2@5466.69,1610.98 5528.72,1673 5612,1673 5654,1631 TP7.1@5654,1534
NetD5_2: D5.2 K1.2 Q5.3 | length 693.2
  Bottom Layer w20: K1.2@2525.79,611.22 2676.78,611.22 2784,504 2784,392 2835.53,340.47 D5.2@2880,340.47 2917.53,340.47 2983.24,274.76 Q5.3@3014,274.76
NetD6_1: D6.1 D7.1 R20.2 R25.2 | length 444
  Bottom Layer w20: R25.2@1885,1399.09 1887,1401.09 R20.2@1995,1401.09 2057.09,1339 D7.1@2146.04,1339
  Bottom Layer w30: R20.2@1995,1401.09 2001.04,1407.13 D6.1@2001.04,1555
NetD8_2: D8.2 R23.2 | length 137.1
  Bottom Layer w20: R23.2@5348.5,414 5348.5,433.5 5366.5,451.5 5424.5,451.5 5433.31,460.31 D8.2@5433.31,482
NetD9_2: D9.2 Q5.1 R31.2 R39.2 | length 222.2
  Bottom Layer w20: Q5.1@2976.6,369.24 2976.6,436.29 D9.2@2977.31,437 R39.2@3061.5,437 R31.2@3061.5,507
NetD10_1: D10.1 R39.1 | length 144.5
  Bottom Layer w20: R39.1@3124.5,437 3124.5,386.5 3141,370 D10.1@3141,299.31
NetF1_1: F1.1 F1.2 J1.1 TP1.1 | length 236.9
  Top Layer w25: TP1.1@125,745 130.57,739.43 F1.1@359.61,739.43
NetHS1_1: HS1.1 R40.2 | length 902.8
  Top Layer w20: HS1.1@2688,1951 2688,2108 2927,2347 v1(3142,2347)
  Bottom Layer w20: v1(3142,2347) 3243,2448 R40.2@3243,2498
NetJ1_3: J1.3 K1.1 RCL1.1 RV1.1 TP2.1
NetQ2_1: Q2.1 R15.2 R16.2 | length 331
  Bottom Layer w20: R15.2@4570,233.5 4607.5,233.5 4624,217 4681,217 ; Q2.1@4707.4,170.76 4707.4,190.6 4681,217 ; R16.2@4773.5,330 4773.5,301.5 4689,217 4681,217
NetQ2_3: Q2.3 R18.1 | length 97.5
  Bottom Layer w20: R18.1@4635.5,333 4634,331.5 4634,277 4645.76,265.24 Q2.3@4670,265.24
NetQ3_3: Q3.3 R16.1 | length 85.7
  Bottom Layer w20: Q3.3@4808,266.24 4825.24,266.24 4836.5,277.5 R16.1@4836.5,330
NetQ4_2: Q4.2 R14.1 | length 73.1
  Bottom Layer w20: R14.1@5580,599.5 5580,608.16 Q4.2@5625.6,653.76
